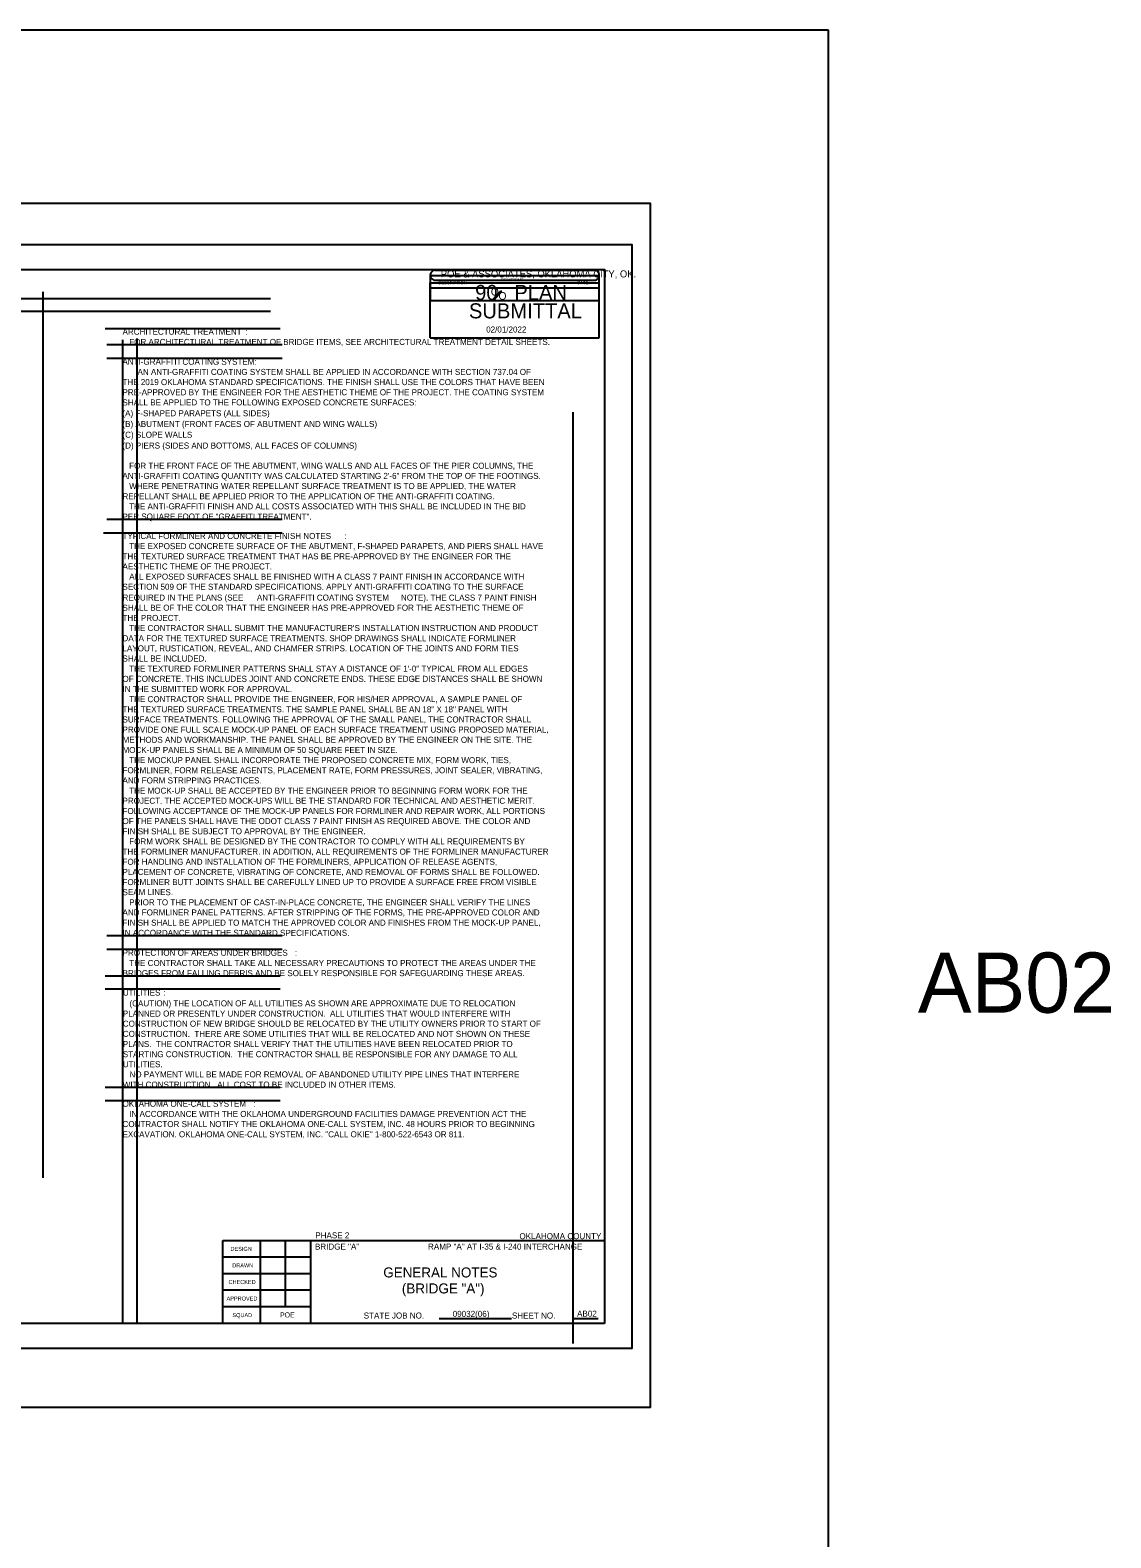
# Model space of a CAD drawing. Extents: x 12306 to 12361.5, y 578.9 to 640.4.
# Drawn here: x 12340.01 to 12361.54, y 610.31 to 640.36 of the extents above; entities that cross this region are included whole.
import ezdxf

# ---------------------------------------------------------------- set-up
doc = ezdxf.new("R2010")
doc.units = 0
for name, color, linetype in [('S', 7, 'Continuous'), ('SHT_Plot_Shape_Full', 7, 'Continuous'), ('SHT_Plot_Shape_Half', 7, 'Continuous'), ('SHT_Sheet_Border', 7, 'Continuous'), ('SHT_Stamp_90_Submit', 7, 'Continuous'), ('SHT_Stamp_Rev_Block', 7, 'Continuous'), ('SHT_Standard_Sheet_Lines', 7, 'Continuous'), ('SHT_Standard_Sheet_Txt', 7, 'Continuous'), ('T', 7, 'Continuous'), ('T-Title', 7, 'Continuous')]:
    doc.layers.add(name, color=color, linetype=linetype)

msp = doc.modelspace()

# ---------------------------------------------------------------- linework, layer by layer
at = {"layer": 'Defpoints'}
for p, q in [((12340.263, 635.145), (12340.263, 617.489)), ((12319.948, 635.01), (12344.799, 635.01)), ((12319.948, 634.76), (12344.799, 634.76)), ((12344.991, 634.408), (12341.502, 634.408)), ((12345.028, 634.085), (12341.539, 634.085)), ((12341.85, 634.185), (12341.85, 614.587)), ((12342.134, 634.213), (12342.134, 614.587)), ((12345.028, 633.815), (12341.539, 633.815)), ((12350.821, 632.745), (12350.821, 614.183)), ((12344.96, 630.335), (12341.471, 630.335)), ((12345.03, 630.605), (12341.54, 630.605)), ((12345.03, 630.335), (12341.54, 630.335)), ((12345.03, 622.309), (12341.54, 622.309)), ((12345.03, 622.04), (12341.54, 622.04)), ((12344.991, 621.506), (12341.502, 621.506)), ((12344.991, 621.244), (12341.502, 621.244)), ((12344.991, 619.285), (12341.502, 619.285)), ((12344.991, 619.023), (12341.502, 619.023))]:
    msp.add_line(p, q, dxfattribs=at)
at = {"layer": 'S'}
msp.add_lwpolyline([(12355.912, 640.357), (12312.476, 640.357), (12312.476, 578.901), (12355.912, 578.901)], close=True, dxfattribs=at)
at = {"layer": 'SHT_Plot_Shape_Full'}
msp.add_lwpolyline([(12316.36, 636.912), (12352.36, 636.912), (12352.36, 612.912), (12316.36, 612.912)], close=True, dxfattribs=at)
at = {"layer": 'SHT_Plot_Shape_Half'}
msp.add_lwpolyline([(12317.998, 636.087), (12351.998, 636.087), (12351.998, 614.087), (12317.998, 614.087)], close=True, dxfattribs=at)
at = {"layer": 'SHT_Sheet_Border'}
for p, q in [((12343.848, 614.587), (12343.848, 616.237)), ((12343.848, 616.237), (12351.448, 616.237)), ((12345.598, 614.587), (12345.598, 616.238))]:
    msp.add_line(p, q, dxfattribs=at)
msp.add_lwpolyline([(12351.448, 614.587), (12319.948, 614.587), (12319.948, 635.587), (12351.448, 635.587)], close=True, dxfattribs=at)
at = {"layer": 'SHT_Stamp_90_Submit'}
for p, q in [((12348.079, 635.572), (12351.245, 635.572)), ((12347.979, 635.322), (12351.345, 635.322)), ((12347.979, 634.223), (12347.979, 635.322)), ((12348.079, 635.372), (12351.245, 635.372)), ((12349.222, 634.984), (12349.377, 635.157)), ((12349.24, 634.984), (12349.395, 635.157)), ((12349.245, 634.984), (12349.4, 635.157)), ((12349.252, 634.984), (12349.408, 635.157)), ((12349.377, 635.157), (12349.408, 635.157)), ((12351.345, 634.223), (12351.345, 635.322)), ((12349.222, 634.984), (12349.252, 634.984)), ((12347.979, 634.223), (12351.345, 634.223))]:
    msp.add_line(p, q, dxfattribs=at)
for centre, start, end in [((12348.079, 635.473), 89.9952, 270), ((12351.245, 635.473), 270, 90.0048)]:
    msp.add_arc(centre, 0.1, start, end, dxfattribs=at)
at = {"layer": 'SHT_Stamp_Rev_Block'}
for p, q in [((12347.979, 635.463), (12347.979, 634.963)), ((12351.345, 635.463), (12347.979, 635.463)), ((12351.345, 634.963), (12351.345, 635.463)), ((12351.345, 635.213), (12347.979, 635.213)), ((12351.345, 634.963), (12347.979, 634.963))]:
    msp.add_line(p, q, dxfattribs=at)
at = {"layer": 'SHT_Standard_Sheet_Lines'}
for p, q in [((12344.598, 614.587), (12344.598, 616.238)), ((12345.098, 614.917), (12345.098, 616.238)), ((12348.159, 614.683), (12349.599, 614.683)), ((12350.823, 614.683), (12351.326, 614.683))]:
    msp.add_line(p, q, dxfattribs=at)
for points in [[(12345.598, 615.907), (12343.848, 615.907)], [(12345.598, 615.577), (12343.848, 615.577)], [(12345.598, 615.247), (12343.848, 615.247)], [(12345.598, 614.917), (12343.848, 614.917)]]:
    msp.add_lwpolyline(points, dxfattribs=at)

# ---------------------------------------------------------------- texts
at = {"layer": 'SHT_Stamp_90_Submit'}
for s, height, p in [('POE & ASSOCIATES, OKLAHOMA CITY, OK.', 0.14, (12348.189, 635.43)), ('90   PLAN', 0.3, (12348.874, 634.98)), ('O', 0.153, (12349.187, 635.069)), ('SUBMITTAL', 0.3, (12348.75, 634.614)), ('O', 0.153, (12349.339, 634.985)), ('02/01/2022', 0.12, (12349.093, 634.332))]:
    msp.add_text(s, height=height, rotation=360, dxfattribs=at).set_placement(p)
at = {"layer": 'SHT_Stamp_Rev_Block'}
for s, p in [('DESCRIPTION', (12348.139, 635.291)), ('REVISIONS', (12349.388, 635.35)), ('DATE', (12350.908, 635.295))]:
    msp.add_text(s, height=0.06, dxfattribs=at).set_placement(p)
at = {"layer": 'SHT_Standard_Sheet_Txt'}
for s, height, p in [('DESIGN', 0.08, (12344, 616.032)), ('DRAWN', 0.08, (12344.035, 615.702)), ('CHECKED', 0.08, (12343.961, 615.372)), ('APPROVED', 0.08, (12343.922, 615.041)), ('SQUAD', 0.08, (12344.039, 614.711)), ('STATE JOB NO.', 0.12, (12346.654, 614.683)), ('SHEET NO. ', 0.12, (12349.607, 614.683))]:
    msp.add_text(s, height=height, dxfattribs=at).set_placement(p)
at = {"layer": 'T'}
for s, height, p in [('ARCHITECTURAL TREATMENT', 0.12, (12341.85, 634.288)), (':', 0.12, (12344.302, 634.288)), ('   FOR ARCHITECTURAL TREATMENT OF BRIDGE ITEMS, SEE ARCHITECTURAL TREATMENT DETAIL SHEETS.', 0.12, (12341.85, 634.085)), ('ANTI-GRAFFITI COATING SYSTEM:', 0.12, (12341.848, 633.689)), ('THE 2019 OKLAHOMA STANDARD SPECIFICATIONS. THE FINISH SHALL USE THE COLORS THAT HAVE BEEN ', 0.12, (12341.848, 633.284)), ('AN ANTI-GRAFFITI COATING SYSTEM SHALL BE APPLIED IN ACCORDANCE WITH SECTION 737.04 OF ', 0.12, (12342.148, 633.487)), ('PRE-APPROVED BY THE ENGINEER FOR THE AESTHETIC THEME OF THE PROJECT. THE COATING SYSTEM ', 0.12, (12341.848, 633.082)), ('SHALL BE APPLIED TO THE FOLLOWING EXPOSED CONCRETE SURFACES:', 0.12, (12341.848, 632.879)), ('(A) F-SHAPED PARAPETS (ALL SIDES)', 0.12, (12341.848, 632.664)), ('(B) ABUTMENT (FRONT FACES OF ABUTMENT AND WING WALLS)', 0.12, (12341.848, 632.45)), ('(C) SLOPE WALLS', 0.12, (12341.848, 632.235)), ('(D) PIERS (SIDES AND BOTTOMS, ALL FACES OF COLUMNS)', 0.12, (12341.848, 632.02)), ('ANTI-GRAFFITI COATING QUANTITY WAS CALCULATED STARTING 2\'-6" FROM THE TOP OF THE FOOTINGS.', 0.12, (12341.848, 631.415)), ('   FOR THE FRONT FACE OF THE ABUTMENT, WING WALLS AND ALL FACES OF THE PIER COLUMNS, THE ', 0.12, (12341.848, 631.618)), ('   WHERE PENETRATING WATER REPELLANT SURFACE TREATMENT IS TO BE APPLIED, THE WATER ', 0.12, (12341.848, 631.213)), ('REPELLANT SHALL BE APPLIED PRIOR TO THE APPLICATION OF THE ANTI-GRAFFITI COATING.', 0.12, (12341.848, 631.01)), ('PER SQUARE FOOT OF "GRAFFITI TREATMENT".', 0.12, (12341.848, 630.605)), ('   THE ANTI-GRAFFITI FINISH AND ALL COSTS ASSOCIATED WITH THIS SHALL BE INCLUDED IN THE BID ', 0.12, (12341.848, 630.808)), ('TYPICAL FORMLINER AND CONCRETE FINISH NOTES', 0.12, (12341.849, 630.218)), ('   THE EXPOSED CONCRETE SURFACE OF THE ABUTMENT, F-SHAPED PARAPETS, AND PIERS SHALL HAVE ', 0.12, (12341.849, 630.015)), (':', 0.12, (12346.267, 630.218)), ('THE TEXTURED SURFACE TREATMENT THAT HAS BE PRE-APPROVED BY THE ENGINEER FOR THE ', 0.12, (12341.849, 629.813)), ('AESTHETIC THEME OF THE PROJECT.', 0.12, (12341.849, 629.61)), ('   ALL EXPOSED SURFACES SHALL BE FINISHED WITH A CLASS 7 PAINT FINISH IN ACCORDANCE WITH ', 0.12, (12341.849, 629.408)), ('SECTION 509 OF THE STANDARD SPECIFICATIONS. APPLY ANTI-GRAFFITI COATING TO THE SURFACE ', 0.12, (12341.849, 629.205)), ('SHALL BE OF THE COLOR THAT THE ENGINEER HAS PRE-APPROVED FOR THE AESTHETIC THEME OF ', 0.12, (12341.849, 628.788)), ('REQUIRED IN THE PLANS (SEE ', 0.12, (12341.849, 628.99)), ('ANTI-GRAFFITI COATING SYSTEM', 0.12, (12344.526, 628.99)), (' NOTE). THE CLASS 7 PAINT FINISH ', 0.12, (12347.351, 628.99)), ('THE PROJECT.', 0.12, (12341.849, 628.585)), ('DATA FOR THE TEXTURED SURFACE TREATMENTS. SHOP DRAWINGS SHALL INDICATE FORMLINER ', 0.12, (12341.849, 628.18)), ("   THE CONTRACTOR SHALL SUBMIT THE MANUFACTURER'S INSTALLATION INSTRUCTION AND PRODUCT ", 0.12, (12341.849, 628.383)), ('LAYOUT, RUSTICATION, REVEAL, AND CHAMFER STRIPS. LOCATION OF THE JOINTS AND FORM TIES ', 0.12, (12341.849, 627.978)), ('SHALL BE INCLUDED.', 0.12, (12341.849, 627.776)), ('   THE TEXTURED FORMLINER PATTERNS SHALL STAY A DISTANCE OF 1\'-0" TYPICAL FROM ALL EDGES ', 0.12, (12341.849, 627.574)), ('OF CONCRETE. THIS INCLUDES JOINT AND CONCRETE ENDS. THESE EDGE DISTANCES SHALL BE SHOWN ', 0.12, (12341.849, 627.371)), ('IN THE SUBMITTED WORK FOR APPROVAL.', 0.12, (12341.849, 627.169)), ('   THE CONTRACTOR SHALL PROVIDE THE ENGINEER, FOR HIS/HER APPROVAL, A SAMPLE PANEL OF ', 0.12, (12341.849, 626.966)), ('THE TEXTURED SURFACE TREATMENTS. THE SAMPLE PANEL SHALL BE AN 18" X 18" PANEL WITH ', 0.12, (12341.849, 626.764)), ('SURFACE TREATMENTS. FOLLOWING THE APPROVAL OF THE SMALL PANEL, THE CONTRACTOR SHALL ', 0.12, (12341.849, 626.561)), ('PROVIDE ONE FULL SCALE MOCK-UP PANEL OF EACH SURFACE TREATMENT USING PROPOSED MATERIAL, ', 0.12, (12341.849, 626.359)), ('METHODS AND WORKMANSHIP. THE PANEL SHALL BE APPROVED BY THE ENGINEER ON THE SITE. THE ', 0.12, (12341.849, 626.156)), ('MOCK-UP PANELS SHALL BE A MINIMUM OF 50 SQUARE FEET IN SIZE.', 0.12, (12341.849, 625.954)), ('   THE MOCKUP PANEL SHALL INCORPORATE THE PROPOSED CONCRETE MIX, FORM WORK, TIES, ', 0.12, (12341.849, 625.751)), ('FORMLINER, FORM RELEASE AGENTS, PLACEMENT RATE, FORM PRESSURES, JOINT SEALER, VIBRATING, ', 0.12, (12341.849, 625.549)), ('AND FORM STRIPPING PRACTICES.', 0.12, (12341.849, 625.346)), ('   THE MOCK-UP SHALL BE ACCEPTED BY THE ENGINEER PRIOR TO BEGINNING FORM WORK FOR THE ', 0.12, (12341.849, 625.143)), ('PROJECT. THE ACCEPTED MOCK-UPS WILL BE THE STANDARD FOR TECHNICAL AND AESTHETIC MERIT. ', 0.12, (12341.849, 624.941)), ('OF THE PANELS SHALL HAVE THE ODOT CLASS 7 PAINT FINISH AS REQUIRED ABOVE. THE COLOR AND ', 0.12, (12341.849, 624.536)), ('FOLLOWING ACCEPTANCE OF THE MOCK-UP PANELS FOR FORMLINER AND REPAIR WORK, ALL PORTIONS ', 0.12, (12341.849, 624.738)), ('FINISH SHALL BE SUBJECT TO APPROVAL BY THE ENGINEER.', 0.12, (12341.849, 624.333)), ('THE FORMLINER MANUFACTURER. IN ADDITION, ALL REQUIREMENTS OF THE FORMLINER MANUFACTURER ', 0.12, (12341.849, 623.928)), ('   FORM WORK SHALL BE DESIGNED BY THE CONTRACTOR TO COMPLY WITH ALL REQUIREMENTS BY ', 0.12, (12341.849, 624.131)), ('FOR HANDLING AND INSTALLATION OF THE FORMLINERS, APPLICATION OF RELEASE AGENTS, ', 0.12, (12341.849, 623.725)), ('PLACEMENT OF CONCRETE, VIBRATING OF CONCRETE, AND REMOVAL OF FORMS SHALL BE FOLLOWED. ', 0.12, (12341.849, 623.523)), ('FORMLINER BUTT JOINTS SHALL BE CAREFULLY LINED UP TO PROVIDE A SURFACE FREE FROM VISIBLE ', 0.12, (12341.849, 623.32)), ('SEAM LINES.', 0.12, (12341.849, 623.12)), ('AND FORMLINER PANEL PATTERNS. AFTER STRIPPING OF THE FORMS, THE PRE-APPROVED COLOR AND ', 0.12, (12341.849, 622.715)), ('   PRIOR TO THE PLACEMENT OF CAST-IN-PLACE CONCRETE, THE ENGINEER SHALL VERIFY THE LINES ', 0.12, (12341.849, 622.917)), ('FINISH SHALL BE APPLIED TO MATCH THE APPROVED COLOR AND FINISHES FROM THE MOCK-UP PANEL, ', 0.12, (12341.849, 622.512)), ('IN ACCORDANCE WITH THE STANDARD SPECIFICATIONS.', 0.12, (12341.849, 622.309)), ('PROTECTION OF AREAS UNDER BRIDGES', 0.12, (12341.851, 621.912)), (':', 0.12, (12345.284, 621.912)), ('AB02', 1.2, (12357.692, 620.777)), ('BRIDGES FROM FALLING DEBRIS AND BE SOLELY RESPONSIBLE FOR SAFEGUARDING THESE AREAS.', 0.12, (12341.851, 621.506)), ('   THE CONTRACTOR SHALL TAKE ALL NECESSARY PRECAUTIONS TO PROTECT THE AREAS UNDER THE ', 0.12, (12341.851, 621.709)), ('UTILITIES', 0.12, (12341.855, 621.119)), ('   (CAUTION) THE LOCATION OF ALL UTILITIES AS SHOWN ARE APPROXIMATE DUE TO RELOCATION ', 0.12, (12341.855, 620.904)), (':', 0.12, (12342.667, 621.119)), ('PLANNED OR PRESENTLY UNDER CONSTRUCTION.  ALL UTILITIES THAT WOULD INTERFERE WITH ', 0.12, (12341.855, 620.701)), ('CONSTRUCTION OF NEW BRIDGE SHOULD BE RELOCATED BY THE UTILITY OWNERS PRIOR TO START OF ', 0.12, (12341.855, 620.499)), ('CONSTRUCTION.  THERE ARE SOME UTILITIES THAT WILL BE RELOCATED AND NOT SHOWN ON THESE', 0.12, (12341.855, 620.296)), ('PLANS.  THE CONTRACTOR SHALL VERIFY THAT THE UTILITIES HAVE BEEN RELOCATED PRIOR TO ', 0.12, (12341.855, 620.094)), ('STARTING CONSTRUCTION.  THE CONTRACTOR SHALL BE RESPONSIBLE FOR ANY DAMAGE TO ALL ', 0.12, (12341.855, 619.891)), ('UTILITIES.', 0.12, (12341.855, 619.691)), ('   NO PAYMENT WILL BE MADE FOR REMOVAL OF ABANDONED UTILITY PIPE LINES THAT INTERFERE ', 0.12, (12341.855, 619.488)), ('WITH CONSTRUCTION.  ALL COST TO BE INCLUDED IN OTHER ITEMS. ', 0.12, (12341.855, 619.285)), ('OKLAHOMA ONE-CALL SYSTEM', 0.12, (12341.85, 618.903)), (':', 0.12, (12344.458, 618.903)), ('CONTRACTOR SHALL NOTIFY THE OKLAHOMA ONE-CALL SYSTEM, INC. 48 HOURS PRIOR TO BEGINNING ', 0.12, (12341.85, 618.498)), ('   IN ACCORDANCE WITH THE OKLAHOMA UNDERGROUND FACILITIES DAMAGE PREVENTION ACT THE ', 0.12, (12341.85, 618.701)), ('EXCAVATION. OKLAHOMA ONE-CALL SYSTEM, INC. "CALL OKIE" 1-800-522-6543 OR 811.', 0.12, (12341.85, 618.295)), ('PHASE 2', 0.12, (12345.69, 616.281)), ('OKLAHOMA COUNTY', 0.12, (12349.756, 616.265)), ('BRIDGE "A"', 0.12, (12345.683, 616.057)), ('RAMP "A" AT I-35 & I-240 INTERCHANGE', 0.12, (12347.935, 616.057)), ('POE', 0.1, (12344.987, 614.705)), ('09032(06)', 0.12, (12348.427, 614.716)), ('AB02', 0.12, (12350.904, 614.721))]:
    msp.add_text(s, height=height, dxfattribs=at).set_placement(p)
at = {"layer": 'T-Title'}
for s, p in [('GENERAL NOTES', (12347.044, 615.502)), ('(BRIDGE "A")', (12347.414, 615.183))]:
    msp.add_text(s, height=0.2, dxfattribs=at).set_placement(p)

doc.saveas('drawing.dxf')
